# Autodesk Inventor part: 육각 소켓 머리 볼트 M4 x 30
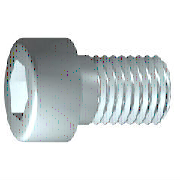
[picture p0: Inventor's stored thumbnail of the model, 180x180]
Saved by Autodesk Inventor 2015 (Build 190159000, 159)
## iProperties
IsCustomPart: 1
Created: 2012-02
Part Number: 육각 소켓 머리 볼트 M4 x 30
Material: 강철, 연강
Description: 원통형 머리 캡 나사
Document SubType Name: Modeling
Standard: JIS B 1176
Designer: mdu-01
Standards Organization: JIS
Language: ko-KR
Size Designation: M4 x 30
Categories: <MemberInstance><Categories><Category DisplayName="조임쇠" InternalName="e4da775c-781d-43d5-af7c-5136215cf5a6" Mnemonic="FSTN"><Category DisplayName="볼트" InternalN
Density: 1 g/cm^3
Appearance: 강철
Author: mdu-01
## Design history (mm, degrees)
sketch "스케치1"
  geometry: L1 (-1, 0)-(30, 0); L2 (30, 0)-(30, 2); L3 (30, 2)-(10, 2); L4 (10, 2)-(9.57, 2); L5 (9.57, 2)-(0, 2); L6 (0, 2)-(0, 3.5); L7 (0, 3.5)-(-4, 3.5); L8 (-4, 3.5)-(-4, 1.732); L9 (-4, 1.732)-(-2, 1.732); L10 (-2, 1.732)-(-1, 0); L11 (-10.8, 0)-(36.8, 0) reference; L12 (0, -0.7)-(0, 4.2) reference; L13 (10, 2)-(0, 2)
  constraints: 22 end point, 6 parallel, 2 collinear, 2 perpendicular, 1 horizontal, 1 point on line
  dimensions: "d1" = 20 distance from line of L3.end L2 (= GEL); "d2" = 0.42952 distance of L4.end L3.end (computed from GAL); "d3" = 4 distance between parallel lines of L8 L6 (= KOH); "d4" = 2 distance of L8.end L9.end (= INTI); "d5" = 60 deg angle of L10 L1; "d6" = 4 diameter of L3 L1 (= GD); "d7" = 4 diameter of L5 L1 (= BDM); "d8" = 3.4641 diameter of L9 L1 (= 1.1547 x SW); "d9" = 7 diameter of L7 L1 (= KOD); "d26" = 30 distance between parallel lines of L12 L2 (= NLG)
revolve "본체" sketch "스케치1" stored, may be unused: angle "d10" = 90 deg
sketch "스케치2"
  geometry: L1 (0, -4.9)-(0, 4.9) reference; L2 (-4.9, 0)-(4.9, 0) reference; L3 (1.732, 0)-(0.866, -1.5); L4 (0.866, -1.5)-(-0.866, -1.5); L5 (-0.866, -1.5)-(-1.732, 0); L6 (-1.732, 0)-(-0.866, 1.5); L7 (-0.866, 1.5)-(0.866, 1.5); L8 (0.866, 1.5)-(1.732, 0); 2 further points
  constraints: 12 end point, 1 coincident, 1 horizontal alignment, 1 point on line, 12 other
extrude "슬롯" join sketch "스케치2" stored distance "d11" = 10; taper "d12" = 0 deg
workplane "Work Plane1"
fillet "Fillet2" dims "d30" = 0.1 (= R)
body "Solid1"
fillet "모깎기1" dims "d17" = 0.4 (= RR)
feature "스레드" dims "d13" = 20 (= GEL), "d14" = 0
chamfer "모따기1" distance "d15" = 0.42941 (= -0.5 x SPD + 0.5 x GD); stored, may be unused: second distance "d16" = 0.42941 (= GUL), angle "d27" = 45 deg
other parameters: "GD" = 4 (= NND) [user parameter; used in 2 equation terms], "NLG" = 30 [user parameter; used in 1 equation term], "GEL" = 20 [user parameter; used in 2 equation terms], "KOD" = 7 [user parameter; used in 1 equation term], "KOH" = 4 [user parameter; used in 1 equation term], "INTI" = 2 [user parameter; used in 1 equation term], "GAL" = 0.42941 (= 0.61345 x PTC) [user parameter; used in 1 equation term], "GUL" = 0.42941 (= 0.61345 x PTC) [user parameter; used in 1 equation term], "BDM" = 4 (= NND) [user parameter; used in 1 equation term], "SW" = 3 [user parameter; used in 2 equation terms], "RR" = 0.4 [user parameter; used in 1 equation term], "SPD" = 3.14117 (= NND - 1.2269 x PTC) [user parameter; used in 1 equation term], "d19" = 0, "d28" = 0, "d29" = 0, "R" = 0.1 [user parameter; used in 1 equation term], "PHH" = 0.2 [user parameter], "GD1" = 3.14117 (= THREADDIA - 1.2269 x PTC) [user parameter], "THREADDIA" = 4 [user parameter; used in 1 equation term], "FAWI" = 45 deg [user parameter], "TPU" = 14.28571 (computed from PTC) [user parameter], "PTC" = 0.7 [user parameter; used in 5 equation terms], "NND" = 4 [user parameter; used in 3 equation terms], "TOA" = 30 deg [user parameter], "E0" = 3.465 (= 1.155 x SW) [user parameter]
